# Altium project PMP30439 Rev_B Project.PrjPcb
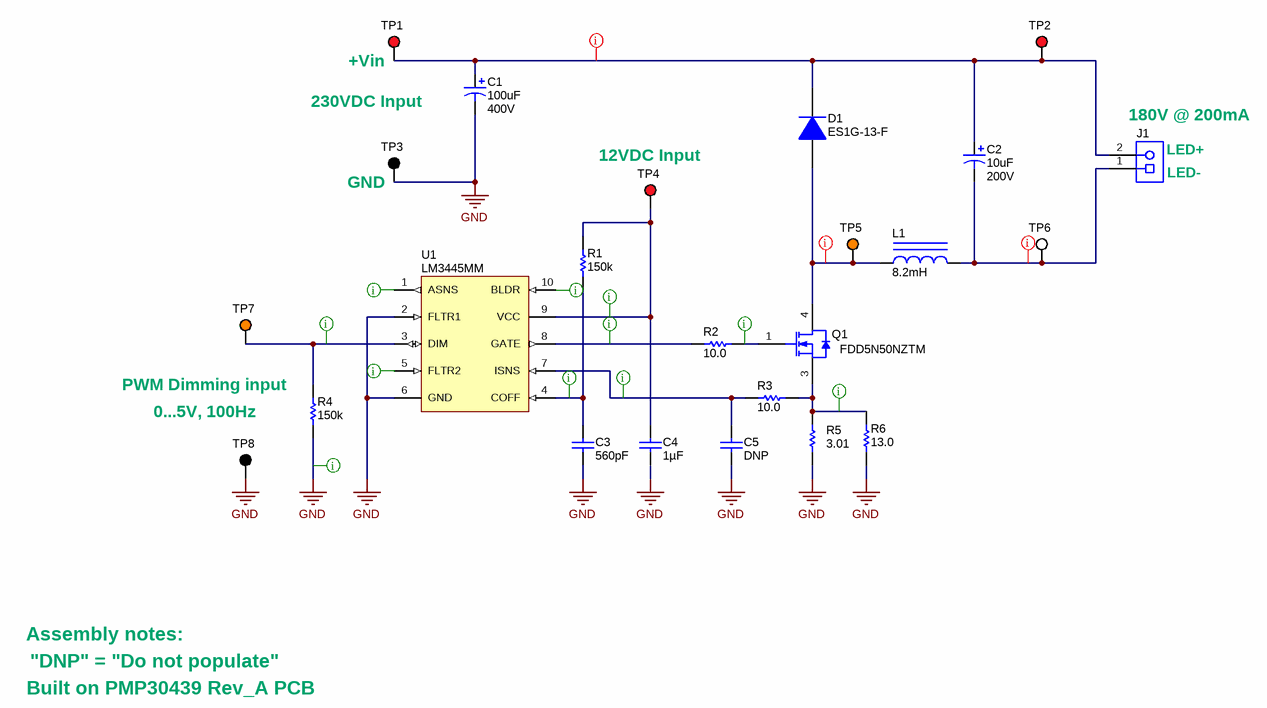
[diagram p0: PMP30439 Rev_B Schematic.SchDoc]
CopyrightYear: 2018; PCB_Layout: R. Scibilia; PCB_Rev: A; PRJ_Engineer: R. Scibilia; PRJ_Number: PMP30439; PRJ_Title: 230VDC input, 180V@200mA LED Driver; SCH_Rev: B; TechSupport: http://www.ti.com/support
1 sheet, 24 parts. Net scope: global (net labels, ports and power ports of the same name join across sheets).
Board file: PMP30439 Rev_A PCB.PcbDoc

## Sheet PMP30439 Rev_B Schematic.SchDoc: 230VDC input, 180V@200mA LED Driver
size A4; Date: Not shown in title block; ApprovedBy: Not shown in title block; CheckedBy: Not shown in title block; Author: Not shown in title block; CompanyName: Not shown in title block; DrawnBy: R. Scibilia; Engineer: Not shown in title block; Organization: Not shown in title block; Address1: Not shown in title block; Address2: Not shown in title block; Address3: Not shown in title block; Address4: Not shown in title block; DocumentNumber: 1; Revision: Use project parameter SCH_Rev; SheetNumber: 1; SheetTotal: 1; PageSetup: Record=PageOptions¦CenterHorizontal=True¦CenterVertical=True¦PrintScale=1.00¦XCorrection=1.00¦YCorrection=1.00¦PrintKind=0¦BorderSize=5000000¦LeftOffset=0¦BottomOffset=0¦Orientation=2¦PaperLength=1000¦PaperWidth=1000¦Scale=100¦PaperSource=15¦PrintQuality=600¦MediaType=1¦DitherType=10¦PaperKind=Letter¦PrintScaleMode=1

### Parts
C1  value 100uF  Value2: 400V  [CAPPR750W80D1600H3000]  (hidden comment: 400KXW100MEFC16X30)
C2  value 10uF  Value2: 200V  [CFX_1000x1600]  (hidden comment: 200CFX10MEFC10X16)
C3  ValueDisplayed: 560pF  [0603]  (hidden comment: C0603C561J5GACTU)
C4  ValueDisplayed: 1µF  [0603]  (hidden comment: 885012206052)
C5  DNP  [0603]
D1  ES1G-13-F  [SMA]
J1  ED555/2DS  [TERM_BLK_ED555-2DS]  (value not drawn)
L1  ValueDisplayed: 8.2mH  [MSS1210]  (hidden comment: MSS1210-825KE)
Q1  FDD5N50NZTM  [DPAK]
R1  ValueDisplayed: 150k  [0603]  (hidden comment: RC0603FR-07150KL)
R2  ValueDisplayed: 10.0  [0603]  (hidden comment: RC0603FR-0710RL)
R3  ValueDisplayed: 10.0  [0603]  (hidden comment: RC0603FR-0710RL)
R4  ValueDisplayed: 150k  [0603]  (hidden comment: RC0603FR-07150KL)
R5  ValueDisplayed: 3.01  [0805_HV]  (hidden comment: RC0805FR-073R01L)
R6  ValueDisplayed: 13.0  [0805_HV]  (hidden comment: CRCW080513R0FKEA)
TP1  5000  [Keystone5000]  (value not drawn)
TP2  5000  [Keystone5000]  (value not drawn)
TP3  5001  [Keystone5001]  (value not drawn)
TP4  5000  [Keystone5000]  (value not drawn)
TP5  5003  [Keystone5003]  (value not drawn)
TP6  5002  [Keystone5002]  (value not drawn)
TP7  5003  [Keystone5003]  (value not drawn)
TP8  5001  [Keystone5001]  (value not drawn)
U1  LM3445MM  [MUB10A_N]

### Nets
GND: C1.2(-) C3.2 C4.2 C5.2 R4.1 R5.1 R6.1 TP3.1 TP8.1 U1.2(FLTR1) U1.6(GND)
NetC1_1: C1.1(+) C2.1(+) D1.1(K) J1.2 TP1.1 TP2.1
NetC2_2: C2.2(-) J1.1 L1.2 TP6.1
NetC3_1: C3.1 R1.1 U1.4(COFF)
NetC4_1: C4.1 R1.2 TP4.1 U1.9(VCC)
NetC5_1: C5.1 R3.1 U1.7(ISNS)
NetD1_2: D1.2(A) L1.1 Q1.4(D) TP5.1
NetQ1_1: Q1.1(G) R2.2
NetQ1_3: Q1.3(S) R3.2 R5.2 R6.2
NetR2_1: R2.1 U1.8(GATE)
NetR4_2: R4.2 TP7.1 U1.3(DIM)

Not connected (* = marked no-connect by the designer): U1 1(ASNS) 5(FLTR2) 10(BLDR)

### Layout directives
rule Clearance Constraint [Generic clearance = 10mil, and 9 value(s) for objects]: GND, NetC4_1, NetC5_1, NetQ1_1, NetQ1_3, NetR2_1, NetR4_2, NetU1_1, NetU1_5, NetU1_10
rule Clearance Constraint [Clearance = 10mil]: NetC3_1
rule Clearance Constraint [Clearance = 20mil]: NetC1_1, NetC2_2, NetD1_2

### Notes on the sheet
- 230VDC Input
- (near TP1) +Vin
- (near J1) 180V @ 200mA
- (near TP3) GND
- (near TP4) 12VDC Input
- (near J1) LED-
- (near J1) LED+
- PWM Dimming input
- 0...5V, 100Hz
- Assembly notes:
- "DNP" = "Do not populate"
- Built on PMP30439 Rev_A PCB

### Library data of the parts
C1 = 400KXW100MEFC16X30: CAP, AL, 100 µF, 400 V, +/- 20%, TH; Manufacturer: Rubycon; Polarized: Y; CompType: Capacitor; ValueDisplayed: 100µF; U/M: EA; Cap_F: 0.0001; Tolerance_%: 20; VDC_V: 400; IRMS_A: 0.58; TaMin_C: -25; TaMax_C: 105; Cap_Case: RCAP, 16x30mm; SizeAreaWB_mm2: 272.25; SizeArea_mm2: 210.25; SizeX_mm: 14.5; SizeZ_mm: 40; AEC Category: Q200; Green_Lifecycle: Not Set; Green_REACh: Incomplete
C2 = 200CFX10MEFC10X16: CAP, AL, 10 µF, 200 V, +/- 20%, TH; Manufacturer: Rubycon; Polarized: Y; CompType: Capacitor; ValueDisplayed: 10µF; U/M: EA; Cap_F: 0.00001; Tolerance_%: 20; VDC_V: 200; IRMS_A: 0.3; TaMin_C: -25; TaMax_C: 105; Cap_Case: 10x16; SizeAreaWB_mm2: 144; SizeArea_mm2: 100; SizeX_mm: 10; SizeZ_mm: 18; AEC Category: Q200
C3 = C0603C561J5GACTU: CAP, CERM, 560 pF, 50 V,+/- 5%, C0G/NP0, 0603; Manufacturer: Kemet; Polarized: N; CompType: Capacitor; Value: 560pF; U/M: EA; Cap_F: 0.00000000056; Tolerance_%: 5; VDC_V: 50; Value2: 50V; TaMin_C: -55; TaMax_C: 125; SizeArea_mm2: 1.28; SizeAreaWB_mm2: 4.68; SizeX_mm: 1.6; SizeY_mm: 0.8; SizeZ_mm: 1; AEC Category: Q200; Green_Lifecycle: Active; Green_REACh: Passed
C4 = 885012206052: CAP, CERM, 1 µF, 16 V,+/- 10%, X7R, 0603; Manufacturer: Wurth Elektronik; Polarized: N; CompType: Capacitor; Value: 1uF; U/M: EA; Cap_F: 0.000001; Tolerance_%: 10; VDC_V: 16; Value2: 16V; TaMin_C: -55; TaMax_C: 125; SizeArea_mm2: 1.28; SizeAreaWB_mm2: 4.68; SizeX_mm: 1.6; SizeY_mm: 0.8; SizeZ_mm: 1; AEC Category: Q200; Green_Lifecycle: Active; Green_REACh: Passed
C5 = C0603C561J5GACTU: CAP, CERM, DNP, 50 V,+/- 5%, C0G/NP0, 0603; Manufacturer: Kemet; Polarized: N; CompType: Capacitor; U/M: EA; Tolerance_%: 5; VDC_V: 50; Value2: 50V; TaMin_C: -55; TaMax_C: 125; SizeArea_mm2: 1.28; SizeAreaWB_mm2: 4.68; SizeX_mm: 1.6; SizeY_mm: 0.8; SizeZ_mm: 1; AEC Category: Q200; Green_Lifecycle: Active; Green_REACh: Passed
D1 = ES1G-13-F: Diode, Superfast Rectifier, 400 V, 1 A, SMA; Manufacturer: Diodes Inc.; U/M: EA; Vf_V: 1.25; Value: 400V; Value1: 1A; Value2: 1.25V; Io_A: 1; Vr_V: 400; TJmax_C: 150; RJC_CperW: 25; SizeAreaWB_mm2: 37.3428; SizeArea_mm2: 16.3228; SizeX_mm: 5.59; SizeY_mm: 2.92; SizeZ_mm: 2.87; AEC Category: Q101; Green_Lifecycle: Active; Green_REACh: Passed
J1 = ED555/2DS: Terminal Block, 3.5mm Pitch, 2x1, TH; Manufacturer: On-Shore Technology; SymbolCreator: a0412235; Pitch_mm: 3.5; Gender: Female; Shrouded: N; Row_Count: 1; ContactFinish: Brass; Current_A: 6; Voltage_V: 150; Cert_CULUS: Y; Green_Lifecycle: Active; Green_REACh: Passed
L1 = MSS1210-825KE: Inductor, Shielded, Ferrite, 8.2 mH, 0.35 A, 6.2 ohm, SMD; Manufacturer: Coilcraft; Value: 8.2mH; Ind_H: 8.2E-3; Imax_A: 0.35; Irms: 0.35A @ 40C rise; Isat: 0.45A @ 30% inductance drop; DCR_ohm: 6.2; Value1: 6.2 ohm; Value2: 0.35A; SizeAreaWB_mm2: 204.49; SizeArea_mm2: 151.29; SizeX_mm: 12.3; SizeZ_mm: 10; AEC Category: Q200; Green_Lifecycle: Not Set; Green_REACh: Incomplete
Q1 = FCD4N60TM: MOSFET, N-CH, 500 V, 4 A, DPAK; Manufacturer: ON Semiconductor; Alternate Manufacturer: None; U/M: EA; ChType: N; VdsMax_V: 500; Value1: 1.5 ohm; Value2: 12 nC; QgTyp_nC: 9; Vgs_V: 30; IdsMax_A: 4; SizeAreaWB_mm2: 101.7114; SizeArea_mm2: 64.8114; SizeX_mm: 9.91; SizeY_mm: 6.54; SizeZ_mm: 2.29; AEC Category: Q101; Green_Lifecycle: Active; Green_REACh: Passed
R1 R4 = RC0603FR-07150KL: RES, 150 k, 1%, 0.1 W, 0603; Manufacturer: Yageo America; CompType: Resistor; Value: 150k; Res_ohm: 150000; Tolerance_%: 1; Power_W: 0.1; Value2: 0.1W; VDC_V: 150; TempCo: 200 ppm/C; SizeArea_mm2: 1.28; SizeX_mm: 1.6; SizeY_mm: 0.8; EIA_Code: E96; U/M: EA; AEC Category: Q200; Green_Lifecycle: Active; Green_REACh: Passed
R2 R3 = RC0603FR-0710RL: RES, 10.0, 1%, 0.1 W, 0603; Manufacturer: Yageo America; CompType: Resistor; Value: 10.0; Res_ohm: 10; Value_Code: 10R0; Tolerance_%: 1; Power_W: 0.1; Value2: 0.1W; VDC_V: 150; TempCo: 200 ppm/C; SizeArea_mm2: 1.28; SizeX_mm: 1.6; SizeY_mm: 0.8; EIA_Code: E96; U/M: EA; AEC Category: Q200; Green_Lifecycle: Active; Green_REACh: Passed
R5 = RC0805FR-073R01L: RES, 3.01, 1%, 0.125 W, 0805; Manufacturer: Yageo America; CompType: Resistor; Value: 3.01; Value_Code: 3R01; Tolerance_%: 1; Power_W: 0.125; Value2: 0.125W; VDC_V: 150; TempCo: 200 ppm/C; SizeArea_mm2: 2.5; SizeX_mm: 2; SizeY_mm: 1.25; SizeZ_mm: 1.45; EIA_Code: E96; U/M: EA; AEC Category: Q200; Green_Lifecycle: Active; Green_REACh: Passed
R6 = CRCW080513R0FKEA: RES, 13.0, 1%, 0.125 W, 0805; Manufacturer: Vishay-Dale; CompType: Resistor; Value: 13.0; Res_ohm: 13; Value_Code: 13R0; Tolerance_%: 1; Power_W: 0.125; Value2: 0.125W; VDC_V: 150; TempCo: 100 ppm/C; SizeArea_mm2: 2.5; SizeX_mm: 2; SizeY_mm: 1.25; SizeZ_mm: 1.45; EIA_Code: E96; U/M: EA; AEC Category: Q200
TP1 TP2 TP4 = 5000: Test Point, Miniature, Red, TH; Manufacturer: Keystone; CompType: Test Point Loop; ContactFinish: Silver; Green_Lifecycle: Active; Green_REACh: Passed
TP3 TP8 = 5001: Test Point, Miniature, Black, TH; Manufacturer: Keystone; CompType: Test Point Loop; ContactFinish: Silver; Green_Lifecycle: Active; Green_REACh: Passed
TP5 TP7 = 5003: Test Point, Miniature, Orange, TH; Manufacturer: Keystone; CompType: Test Point Loop; ContactFinish: Silver; Green_Lifecycle: Active; Green_REACh: Passed
TP6 = 5002: Test Point, Miniature, White, TH; Manufacturer: Keystone; CompType: Test Point Loop; ContactFinish: Silver; Green_Lifecycle: Active; Green_REACh: Passed
U1 = LM3445MM: Triac Dimmable Offline LED Driver, PowerWise, 10-pin MSOP; Manufacturer: Texas Instruments; PackageTopMarking: ZXTT*SULB; PowerWise: Y; CompType: MiscPower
